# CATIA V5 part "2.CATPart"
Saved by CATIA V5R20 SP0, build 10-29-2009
Part number: 2
Bounding box of the stored display mesh (mm): x -44.998 to 144.994, y -73.582 to 105, z -10.5 to 0
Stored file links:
  E:\Ehsan\Amoozesh\CATIA\CATIA Course\Advanced\Videos\Session-15\2.CATPart
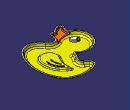
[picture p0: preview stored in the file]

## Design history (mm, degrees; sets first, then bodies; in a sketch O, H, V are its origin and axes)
SheetMetalParameters1: Thickness 0.5, BendRadius 4, KFactor 0.5 {= log(min(100,max(20*SheetMetalParameters1.BendRadius,SheetMetalParameters1.Thickness)/SheetMetalParameters1.Thickness))/log(100)/2}, ReliefRadialLength 1, ReliefAxialLength 2, MinimumBendRadius 0
Body1 (main body)
  Sketch1 on xy-plane, origin (0, 0, 0), H (0, 1, 0), V (-1, 0, 0)
    line L1 (-25, -29.1891) -> (-25, 22.6703)
    arc A1 centre (-48, 38) radius 24 from (-28.6154, 23.8495) to (-60.8957, 17.7589) cw
    point P1 (-48, 38)
    arc A2 centre (-27, 22.6703) radius 2 from (-28.6154, 23.8495) to (-25, 22.6703) cw
    arc A3 centre (-40, 18) radius 29 from (-56.0304, -6.1667) to (-68.4953, 12.6133) cw
    point P5 (-40, 18)
    point P6 (-33.664, -10.2994)
    arc A4 centre (-63.5823, 13.5421) radius 5 from (-68.4953, 12.6133) to (-60.8957, 17.7589) cw
    arc A5 centre (-54, -54.4873) radius 35 from (-28.4595, -30.5566) to (-54.8861, -19.4986) ccw
    point P10 (-54, -54.4873)
    arc A6 centre (-27, -29.1891) radius 2 from (-28.4595, -30.5566) to (-25, -29.1891) ccw
    arc A7 centre (-55, -15) radius 4.5 from (-54.8861, -19.4986) to (-58.2001, -11.8363) cw
    point P16 (-55, -15)
    arc A8 centre (-56.5831, -7) radius 1 from (-56.0304, -6.1667) to (-55.6133, -7.2438) cw
    point P17 (-56.5831, -7)
    arc A9 centre (-65.3116, -4.8058) radius 10 from (-58.2001, -11.8363) to (-55.6133, -7.2438) ccw
    distance L1 V = 25
    distance P1 V = 48
    distance H P1 = 38
    radius A1 = 24
    radius A2 = 2
    distance P5 V = 40
    distance P5 H = 18
    radius A3 = 29
    radius A4 = 5
    radius A5 = 35
    radius A6 = 2
    distance P10 V = 54
    radius A7 = 4.5
    distance H P16 = 15
    distance P16 V = 55
    radius A8 = 1
    distance P17 H = 7
    radius A9 = 10
    vertical: L1 V
    tangency: A2 A1, A2 L1, A4 A3, A4 A1, A6 A5, A6 L1, A7 A5, A8 A3, A9 A8, A9 A7
    coincidence: A3 P6
  Sketch2 on xy-plane, origin (0, 0, 0), H (0, 1, 0), V (-1, 0, 0)
    arc A1 centre (0, 0) radius 40 from (27.6778, -28.878) to (-34.1429, -20.8389) ccw
    point P1 (0, 0)
    point P2 (15, -90)
    ellipse A2 centre (15, -90) semi-axes 80, 50 rotation 0 from (-42.0643, -54.9573) to (91.18, -105.266)
    arc A3 centre (-55.4823, -33.8632) radius 25 from (-34.1429, -20.8389) to (-42.0643, -54.9573) cw
    arc A4 centre (20, -68.7501) radius 80 from (91.18, -105.266) to (93.1478, -36.3556) ccw
    point P7 (20, -68.7501)
    arc A5 centre (112.9434, -69.9268) radius 50 from (70.2946, -43.8293) to (78.7669, -33.4307) cw
    arc A6 centre (14.7964, -85.0041) radius 50 from (29.652, -37.262) to (47.6453, -47.3086) cw
    point P9 (14.7964, -85.0041)
    arc A7 centre (84.9186, -40) radius 9 from (78.7669, -33.4307) to (93.1478, -36.3556) cw
    point P12 (84.9186, -40)
    arc A8 centre (57.5, -36) radius 15 from (70.2946, -43.8293) to (47.6453, -47.3086) cw
    point P15 (57.5, -36)
    arc A9 centre (31.1375, -32.4878) radius 5 from (29.652, -37.262) to (27.6778, -28.878) cw
    radius A1 = 40
    distance P2 V = 15
    distance P2 H = 90
    "Radius" A2 = 80
    "Radius" A2 = 50
    radius A3 = 25
    radius A4 = 80
    radius A5 = 50
    radius A6 = 50
    radius A7 = 9
    radius A8 = 15
    distance P1 V = 0
    radius A9 = 5
    distance P15 V = 57.5
    distance H P15 = 36
    distance P7 V = 20
    distance P9 P2 = 5
    distance H P12 = 40
    coincidence: P1 H
    tangency: A3 A1, A3 A2, A4 A2, A7 A5, A7 A4, A8 A5, A8 A6, A9 A6, A9 A1
    horizontal: A2 H
  Sketch3 on xy-plane, origin (0, 0, 0), H (0, 1, 0), V (-1, 0, 0)
    reference offset curve E1 from Sketch2
    arc A1 centre (-48, 37.9998) radius 18.9998 from (-58.2091, 21.9758) to (-45.1966, 19.2079) ccw
    arc A2 centre (-63.582, 13.5416) radius 10.0002 from (-58.2091, 21.9758) to (-73.4083, 11.6846) ccw
    arc A3 centre (-39.9993, 18.0004) radius 34.0007 from (-73.4083, 11.6846) to (-61.6528, -8.2137) ccw
    line L1 (-61.6528, -8.2137) -> (-61.7558, -8.321)
    arc A4 centre (-54.9995, -14.9998) radius 9.5002 from (-61.7558, -8.321) to (-54.7595, -24.497) ccw
    arc A5 centre (-54.0006, -54.4887) radius 30.0013 from (-41.6606, -27.1427) to (-54.7595, -24.497) ccw
    point P6 (-39.8968, 20.8145)
    point P7 (-35.7354, -30.6882)
    arc A6 centre (-46.672, 29.0985) radius 10 from (-45.1966, 19.2079) to (-38.1862, 23.8078) ccw
    arc A7 centre (-45.7737, -36.2576) radius 10 from (-36.0646, -38.6518) to (-41.6606, -27.1427) ccw
    radius A6 = 10
    radius A7 = 10
    coincidence: E1 P6, E1 P7, A1 P6, A5 P7
    tangency: A6 A1, A6 E1, A7 E1, A7 A5
  Wall1: Thickness 0.5, Profile Sketch3
  d_Stamp1: NewRoot_AttribNormalisation "No Standard", Stamp_FilletRadius 1.5, Stamp_IntersectFilletRadius 2
  d_Stamp2: NewRoot_AttribNormalisation "No Standard", Stamp_FilletRadius 1.5, Stamp_IntersectFilletRadius 2
  d_Stamp3: NewRoot_AttribNormalisation "No Standard", Stamp_FilletRadius 3, Stamp_IntersectFilletRadius 2
  d_Stamp4: NewRoot_AttribNormalisation "No Standard", Stamp_FilletRadius 0.5, Stamp_IntersectFilletRadius 2
  d_Stamp5: NewRoot_AttribNormalisation "No Standard", Stamp_FilletRadius 0.5, Stamp_IntersectFilletRadius 2
  d_Stamp6: NewRoot_AttribNormalisation "No Standard", Stamp_FilletRadius 0.5, Stamp_IntersectFilletRadius 2
  Sketch4 on face of d_Stamp3, origin (0, 0, -5), H (0, 1, 0), V (-1, 0, 0)
    arc A1 centre (13.8132, -61.8517) radius 38.1465 from (5.0417, -98.976) to (45.5272, -83.0501) ccw
    arc A2 centre (14.6393, -44.925) radius 42.9054 from (34.7811, -82.8088) to (7.041, -87.1522) cw
  Sketch5 on face of d_Stamp4, origin (0, 0, -5), H (0, 1, 0), V (-1, 0, 0)
    circle A1 centre (-8, 16.5) radius 3.4
    point P1 (-8, 16.5)
    distance P1 V = 8
    distance P1 H = 16.5
    radius A1 = 3.4
  Sketch6 on face of d_Stamp1, origin (0, 0, -10), H (0, 1, 0), V (-1, 0, 0)
    point P1 (-15, 12)
    ellipse A1 centre (-15, 12) semi-axes 12.5, 8 rotation 46.488
    distance P1 H = 12
    distance P1 V = 15
    "Radius" A1 = 12.5
    "Radius" A1 = 8
  Sketch7 on face of d_Stamp1, origin (0, 0, -10), H (0, 1, 0), V (-1, 0, 0)
    arc A1 centre (0, -85) radius 26 from (15.5316, -64.1489) to (-3.3528, -110.7829) ccw
    point P1 (0, -85)
    arc A2 centre (60, -75) radius 3 from (62.6599, -76.3875) to (59.1736, -72.1161) ccw
    point P2 (60, -75)
    arc A3 centre (5.0293, -46.3256) radius 65 from (62.6599, -76.3875) to (-3.3528, -110.7829) cw
    arc A4 centre (45.4001, -24.0506) radius 50 from (59.1736, -72.1161) to (15.5316, -64.1489) cw
    distance H P2 = 75
    radius A1 = 26
    distance V P2 = 60
    distance P1 H = 85
    radius A3 = 65
    radius A2 = 3
    radius A4 = 50
    tangency: A3 A2, A1 A3, A1 A4, A4 A2
    coincidence: P1 V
